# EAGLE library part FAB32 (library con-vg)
CONNECTOR female, 32 pins, block, type B, row A, grid 2.54 mm
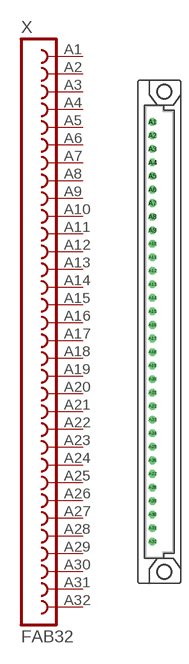
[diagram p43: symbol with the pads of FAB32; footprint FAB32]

Designator prefix X

## FAB32  [FAB32]
A1  1  pas
A2  2  pas
A3  3  pas
A4  4  pas
A5  5  pas
A6  6  pas
A7  7  pas
A8  8  pas
A9  9  pas
A10  10  pas
A11  11  pas
A12  12  pas
A13  13  pas
A14  14  pas
A15  15  pas
A16  16  pas
A17  17  pas
A18  18  pas
A19  19  pas
A20  20  pas
A21  21  pas
A22  22  pas
A23  23  pas
A24  24  pas
A25  25  pas
A26  26  pas
A27  27  pas
A28  28  pas
A29  29  pas
A30  30  pas
A31  31  pas
A32  32  pas

## Footprint FAB32 (pad centres in mm)
CONNECTOR female, 32 pins, type B, row A, grid 2.54 mm
drill 0.914 octagon: A1 -1.27,39.37; A2 -1.27,36.83; A3 -1.27,34.29; A4 -1.27,31.75; A5 -1.27,29.21; A6 -1.27,26.67; A7 -1.27,24.13; A8 -1.27,21.59; A9 -1.27,19.05; A10 -1.27,16.51; A11 -1.27,13.97; A12 -1.27,11.43; A13 -1.27,8.89; A14 -1.27,6.35; A15 -1.27,3.81; A16 -1.27,1.27; A17 -1.27,-1.27; A18 -1.27,-3.81; A19 -1.27,-6.35; A20 -1.27,-8.89; A21 -1.27,-11.43; A22 -1.27,-13.97; A23 -1.27,-16.51; A24 -1.27,-19.05; A25 -1.27,-21.59; A26 -1.27,-24.13; A27 -1.27,-26.67; A28 -1.27,-29.21; A29 -1.27,-31.75; A30 -1.27,-34.29; A31 -1.27,-36.83; A32 -1.27,-39.37
hole 2.794 at 0.965,-45.009
hole 2.794 at 0.965,45.009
